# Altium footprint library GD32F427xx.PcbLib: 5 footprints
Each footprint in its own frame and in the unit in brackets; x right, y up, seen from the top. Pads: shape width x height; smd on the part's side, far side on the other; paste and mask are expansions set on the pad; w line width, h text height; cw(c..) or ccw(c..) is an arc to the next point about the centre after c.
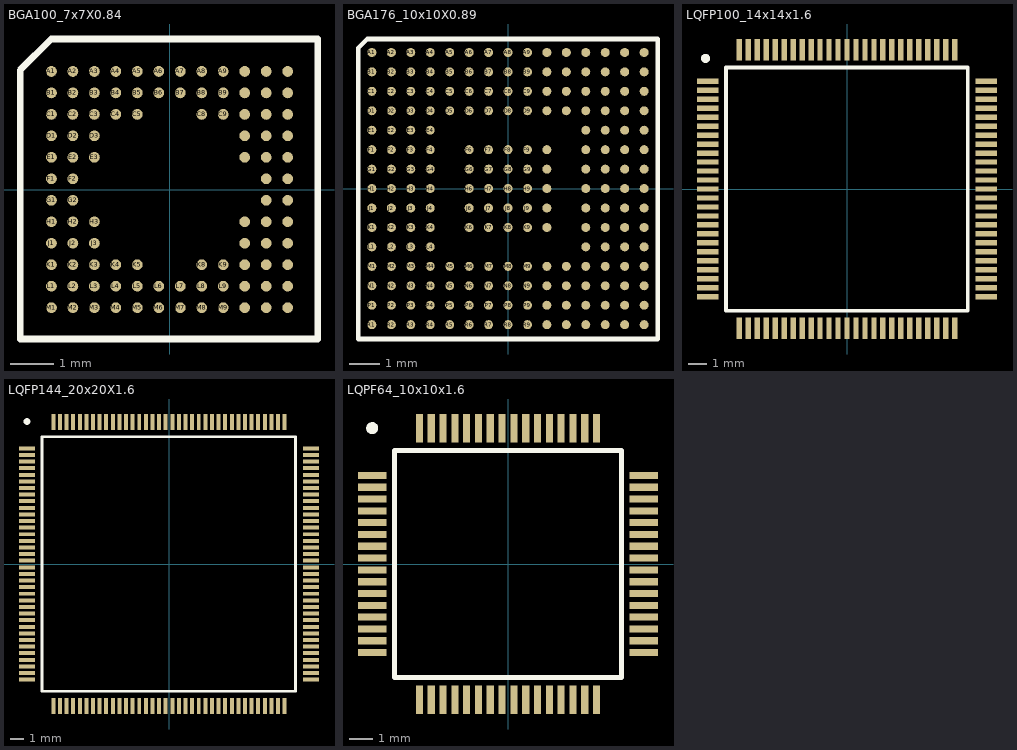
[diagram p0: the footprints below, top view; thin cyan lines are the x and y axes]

## BGA100_7x7X0.84 [mm]
pads (100):
  round 0.25 smd mask+0.05: A1(-2.75,2.75) A2(-2.25,2.75) A3(-1.75,2.75) A4(-1.25,2.75) A5(-0.75,2.75) A6(-0.25,2.75) A7(0.25,2.75) A8(0.75,2.75) A9(1.25,2.75) A10(1.75,2.75) A11(2.25,2.75) A12(2.75,2.75) B1(-2.75,2.25) B2(-2.25,2.25) B3(-1.75,2.25) B4(-1.25,2.25) B5(-0.75,2.25) B6(-0.25,2.25) B7(0.25,2.25) B8(0.75,2.25) B9(1.25,2.25) B10(1.75,2.25) B11(2.25,2.25) B12(2.75,2.25) C1(-2.75,1.75) C2(-2.25,1.75) C3(-1.75,1.75) C4(-1.25,1.75) C5(-0.75,1.75) C8(0.75,1.75) C9(1.25,1.75) C10(1.75,1.75) C11(2.25,1.75) C12(2.75,1.75) D1(-2.75,1.25) D2(-2.25,1.25) D3(-1.75,1.25) D10(1.75,1.25) D11(2.25,1.25) D12(2.75,1.25) E1(-2.75,0.75) E2(-2.25,0.75) E3(-1.75,0.75) E10(1.75,0.75) E11(2.25,0.75) E12(2.75,0.75) F1(-2.75,0.25) F2(-2.25,0.25) F11(2.25,0.25) F12(2.75,0.25) G1(-2.75,-0.25) G2(-2.25,-0.25) G11(2.25,-0.25) G12(2.75,-0.25) H1(-2.75,-0.75) H2(-2.25,-0.75) H3(-1.75,-0.75) H10(1.75,-0.75) H11(2.25,-0.75) H12(2.75,-0.75) J1(-2.75,-1.25) J2(-2.25,-1.25) J3(-1.75,-1.25) J10(1.75,-1.25) J11(2.25,-1.25) J12(2.75,-1.25) K1(-2.75,-1.75) K2(-2.25,-1.75) K3(-1.75,-1.75) K4(-1.25,-1.75) K5(-0.75,-1.75) K8(0.75,-1.75) K9(1.25,-1.75) K10(1.75,-1.75) K11(2.25,-1.75) K12(2.75,-1.75) L1(-2.75,-2.25) L2(-2.25,-2.25) L3(-1.75,-2.25) L4(-1.25,-2.25) L5(-0.75,-2.25) L6(-0.25,-2.25) L7(0.25,-2.25) L8(0.75,-2.25) L9(1.25,-2.25) L10(1.75,-2.25) L11(2.25,-2.25) L12(2.75,-2.25) M1(-2.75,-2.75) M2(-2.25,-2.75) M3(-1.75,-2.75) M4(-1.25,-2.75) M5(-0.75,-2.75) M6(-0.25,-2.75) M7(0.25,-2.75) M8(0.75,-2.75) M9(1.25,-2.75) M10(1.75,-2.75) M11(2.25,-2.75) M12(2.75,-2.75)
Top Overlay:
  lines w0.152: -3.48,-3.48 3.454,-3.48 3.454,3.505 -2.757,3.505 -3.48,2.782 -3.48,-3.48
3D body "BGA100C50P12X12_700X700X84.step": height 0.84, standoff 0, extent -3.5,-3.5 3.5,3.5

## BGA176_10x10X0.89 [mm]
pads (201):
  round 0.3 smd mask+0.05: A1(-4.55,4.55) A2(-3.9,4.55) A3(-3.25,4.55) A4(-2.6,4.55) A5(-1.95,4.55) A6(-1.3,4.55) A7(-0.65,4.55) A8(0,4.55) A9(0.65,4.55) A10(1.3,4.55) A11(1.95,4.55) A12(2.6,4.55) A13(3.25,4.55) A14(3.9,4.55) A15(4.55,4.55) B1(-4.55,3.9) B2(-3.9,3.9) B3(-3.25,3.9) B4(-2.6,3.9) B5(-1.95,3.9) B6(-1.3,3.9) B7(-0.65,3.9) B8(0,3.9) B9(0.65,3.9) B10(1.3,3.9) B11(1.95,3.9) B12(2.6,3.9) B13(3.25,3.9) B14(3.9,3.9) B15(4.55,3.9) C1(-4.55,3.25) C2(-3.9,3.25) C3(-3.25,3.25) C4(-2.6,3.25) C5(-1.95,3.25) C6(-1.3,3.25) C7(-0.65,3.25) C8(0,3.25) C9(0.65,3.25) C10(1.3,3.25) C11(1.95,3.25) C12(2.6,3.25) C13(3.25,3.25) C14(3.9,3.25) C15(4.55,3.25) D1(-4.55,2.6) D2(-3.9,2.6) D3(-3.25,2.6) D4(-2.6,2.6) D5(-1.95,2.6) D6(-1.3,2.6) D7(-0.65,2.6) D8(0,2.6) D9(0.65,2.6) D10(1.3,2.6) D11(1.95,2.6) D12(2.6,2.6) D13(3.25,2.6) D14(3.9,2.6) D15(4.55,2.6) E1(-4.55,1.95) E2(-3.9,1.95) E3(-3.25,1.95) E4(-2.6,1.95) E12(2.6,1.95) E13(3.25,1.95) E14(3.9,1.95) E15(4.55,1.95) F1(-4.55,1.3) F2(-3.9,1.3) F3(-3.25,1.3) F4(-2.6,1.3) F6(-1.3,1.3) F7(-0.65,1.3) F8(0,1.3) F9(0.65,1.3) F10(1.3,1.3) F12(2.6,1.3) F13(3.25,1.3) F14(3.9,1.3) F15(4.55,1.3) G1(-4.55,0.65) G2(-3.9,0.65) G3(-3.25,0.65) G4(-2.6,0.65) G6(-1.3,0.65) G7(-0.65,0.65) G8(0,0.65) G9(0.65,0.65) G10(1.3,0.65) G12(2.6,0.65) G13(3.25,0.65) G14(3.9,0.65) G15(4.55,0.65) H1(-4.55,0) H2(-3.9,0) H3(-3.25,0) H4(-2.6,0) H6(-1.3,0) H7(-0.65,0) H8(0,0) H9(0.65,0) H10(1.3,0) H12(2.6,0) H13(3.25,0) H14(3.9,0) H15(4.55,0) J1(-4.55,-0.65) J2(-3.9,-0.65) J3(-3.25,-0.65) J4(-2.6,-0.65) J6(-1.3,-0.65) J7(-0.65,-0.65) J8(0,-0.65) J9(0.65,-0.65) J10(1.3,-0.65) J12(2.6,-0.65) J13(3.25,-0.65) J14(3.9,-0.65) J15(4.55,-0.65) K1(-4.55,-1.3) K2(-3.9,-1.3) K3(-3.25,-1.3) K4(-2.6,-1.3) K6(-1.3,-1.3) K7(-0.65,-1.3) K8(0,-1.3) K9(0.65,-1.3) K10(1.3,-1.3) K12(2.6,-1.3) K13(3.25,-1.3) K14(3.9,-1.3) K15(4.55,-1.3) L1(-4.55,-1.95) L2(-3.9,-1.95) L3(-3.25,-1.95) L4(-2.6,-1.95) L12(2.6,-1.95) L13(3.25,-1.95) L14(3.9,-1.95) L15(4.55,-1.95) M1(-4.55,-2.6) M2(-3.9,-2.6) M3(-3.25,-2.6) M4(-2.6,-2.6) M5(-1.95,-2.6) M6(-1.3,-2.6) M7(-0.65,-2.6) M8(0,-2.6) M9(0.65,-2.6) M10(1.3,-2.6) M11(1.95,-2.6) M12(2.6,-2.6) M13(3.25,-2.6) M14(3.9,-2.6) M15(4.55,-2.6) N1(-4.55,-3.25) N2(-3.9,-3.25) N3(-3.25,-3.25) N4(-2.6,-3.25) N5(-1.95,-3.25) N6(-1.3,-3.25) N7(-0.65,-3.25) N8(0,-3.25) N9(0.65,-3.25) N10(1.3,-3.25) N11(1.95,-3.25) N12(2.6,-3.25) N13(3.25,-3.25) N14(3.9,-3.25) N15(4.55,-3.25) P1(-4.55,-3.9) P2(-3.9,-3.9) P3(-3.25,-3.9) P4(-2.6,-3.9) P5(-1.95,-3.9) P6(-1.3,-3.9) P7(-0.65,-3.9) P8(0,-3.9) P9(0.65,-3.9) P10(1.3,-3.9) P11(1.95,-3.9) P12(2.6,-3.9) P13(3.25,-3.9) P14(3.9,-3.9) P15(4.55,-3.9) R1(-4.55,-4.55) R2(-3.9,-4.55) R3(-3.25,-4.55) R4(-2.6,-4.55) R5(-1.95,-4.55) R6(-1.3,-4.55) R7(-0.65,-4.55) R8(0,-4.55) R9(0.65,-4.55) R10(1.3,-4.55) R11(1.95,-4.55) R12(2.6,-4.55) R13(3.25,-4.55) R14(3.9,-4.55) R15(4.55,-4.55)
Top Overlay:
  lines w0.152: -5.004,-5.029 -5.004,4.699 -4.703,5 5.004,5 5.004,-5.029 -5.004,-5.029
3D body "BGA176C65P15X15_1000X1000X89.step": height 0.89, standoff 0, extent -5,-5 5,5

## LQFP100_14x14x1.6 [mm]
pads (100):
  rect 1.2x0.3 smd: 1(-7.75,6) 2(-7.75,5.5) 3(-7.75,5) 4(-7.75,4.5) 5(-7.75,4) 6(-7.75,3.5) 7(-7.75,3) 8(-7.75,2.5) 9(-7.75,2) 10(-7.75,1.5) 11(-7.75,1) 12(-7.75,0.5) 13(-7.75,0) 14(-7.75,-0.5) 15(-7.75,-1) 16(-7.75,-1.5) 17(-7.75,-2) 18(-7.75,-2.5) 19(-7.75,-3) 20(-7.75,-3.5) 21(-7.75,-4) 22(-7.75,-4.5) 23(-7.75,-5) 24(-7.75,-5.5) 25(-7.75,-6) 51(7.75,-6) 52(7.75,-5.5) 53(7.75,-5) 54(7.75,-4.5) 55(7.75,-4) 56(7.75,-3.5) 57(7.75,-3) 58(7.75,-2.5) 59(7.75,-2) 60(7.75,-1.5) 61(7.75,-1) 62(7.75,-0.5) 63(7.75,0) 64(7.75,0.5) 65(7.75,1) 66(7.75,1.5) 67(7.75,2) 68(7.75,2.5) 69(7.75,3) 70(7.75,3.5) 71(7.75,4) 72(7.75,4.5) 73(7.75,5) 74(7.75,5.5) 75(7.75,6)
  rect 0.3x1.2 smd: 26(-6,-7.75) 27(-5.5,-7.75) 28(-5,-7.75) 29(-4.5,-7.75) 30(-4,-7.75) 31(-3.5,-7.75) 32(-3,-7.75) 33(-2.5,-7.75) 34(-2,-7.75) 35(-1.5,-7.75) 36(-1,-7.75) 37(-0.5,-7.75) 38(0,-7.75) 39(0.5,-7.75) 40(1,-7.75) 41(1.5,-7.75) 42(2,-7.75) 43(2.5,-7.75) 44(3,-7.75) 45(3.5,-7.75) 46(4,-7.75) 47(4.5,-7.75) 48(5,-7.75) 49(5.5,-7.75) 50(6,-7.75) 76(6,7.75) 77(5.5,7.75) 78(5,7.75) 79(4.5,7.75) 80(4,7.75) 81(3.5,7.75) 82(3,7.75) 83(2.5,7.75) 84(2,7.75) 85(1.5,7.75) 86(1,7.75) 87(0.5,7.75) 88(0,7.75) 89(-0.5,7.75) 90(-1,7.75) 91(-1.5,7.75) 92(-2,7.75) 93(-2.5,7.75) 94(-3,7.75) 95(-3.5,7.75) 96(-4,7.75) 97(-4.5,7.75) 98(-5,7.75) 99(-5.5,7.75) 100(-6,7.75)
Top Overlay:
  circle w0.254: c-7.877,7.27 r0.127
  lines w0.203: -6.734,-6.782 6.728,-6.782 6.728,6.762 -6.734,6.762 -6.734,-6.782
3D body "TSQFP50P1600X1600X160-100N.step": height 1.6, standoff 0, extent -8,-8 8,8

## LQFP144_20x20X1.6 [mm]
pads (144):
  rect 1.2x0.3 smd: 1(-10.75,8.75) 2(-10.75,8.25) 3(-10.75,7.75) 4(-10.75,7.25) 5(-10.75,6.75) 6(-10.75,6.25) 7(-10.75,5.75) 8(-10.75,5.25) 9(-10.75,4.75) 10(-10.75,4.25) 11(-10.75,3.75) 12(-10.75,3.25) 13(-10.75,2.75) 14(-10.75,2.25) 15(-10.75,1.75) 16(-10.75,1.25) 17(-10.75,0.75) 18(-10.75,0.25) 19(-10.75,-0.25) 20(-10.75,-0.75) 21(-10.75,-1.25) 22(-10.75,-1.75) 23(-10.75,-2.25) 24(-10.75,-2.75) 25(-10.75,-3.25) 26(-10.75,-3.75) 27(-10.75,-4.25) 28(-10.75,-4.75) 29(-10.75,-5.25) 30(-10.75,-5.75) 31(-10.75,-6.25) 32(-10.75,-6.75) 33(-10.75,-7.25) 34(-10.75,-7.75) 35(-10.75,-8.25) 36(-10.75,-8.75) 73(10.75,-8.75) 74(10.75,-8.25) 75(10.75,-7.75) 76(10.75,-7.25) 77(10.75,-6.75) 78(10.75,-6.25) 79(10.75,-5.75) 80(10.75,-5.25) 81(10.75,-4.75) 82(10.75,-4.25) 83(10.75,-3.75) 84(10.75,-3.25) 85(10.75,-2.75) 86(10.75,-2.25) 87(10.75,-1.75) 88(10.75,-1.25) 89(10.75,-0.75) 90(10.75,-0.25) 91(10.75,0.25) 92(10.75,0.75) 93(10.75,1.25) 94(10.75,1.75) 95(10.75,2.25) 96(10.75,2.75) 97(10.75,3.25) 98(10.75,3.75) 99(10.75,4.25) 100(10.75,4.75) 101(10.75,5.25) 102(10.75,5.75) 103(10.75,6.25) 104(10.75,6.75) 105(10.75,7.25) 106(10.75,7.75) 107(10.75,8.25) 108(10.75,8.75)
  rect 0.3x1.2 smd: 37(-8.75,-10.75) 38(-8.25,-10.75) 39(-7.75,-10.75) 40(-7.25,-10.75) 41(-6.75,-10.75) 42(-6.25,-10.75) 43(-5.75,-10.75) 44(-5.25,-10.75) 45(-4.75,-10.75) 46(-4.25,-10.75) 47(-3.75,-10.75) 48(-3.25,-10.75) 49(-2.75,-10.75) 50(-2.25,-10.75) 51(-1.75,-10.75) 52(-1.25,-10.75) 53(-0.75,-10.75) 54(-0.25,-10.75) 55(0.25,-10.75) 56(0.75,-10.75) 57(1.25,-10.75) 58(1.75,-10.75) 59(2.25,-10.75) 60(2.75,-10.75) 61(3.25,-10.75) 62(3.75,-10.75) 63(4.25,-10.75) 64(4.75,-10.75) 65(5.25,-10.75) 66(5.75,-10.75) 67(6.25,-10.75) 68(6.75,-10.75) 69(7.25,-10.75) 70(7.75,-10.75) 71(8.25,-10.75) 72(8.75,-10.75) 109(8.75,10.75) 110(8.25,10.75) 111(7.75,10.75) 112(7.25,10.75) 113(6.75,10.75) 114(6.25,10.75) 115(5.75,10.75) 116(5.25,10.75) 117(4.75,10.75) 118(4.25,10.75) 119(3.75,10.75) 120(3.25,10.75) 121(2.75,10.75) 122(2.25,10.75) 123(1.75,10.75) 124(1.25,10.75) 125(0.75,10.75) 126(0.25,10.75) 127(-0.25,10.75) 128(-0.75,10.75) 129(-1.25,10.75) 130(-1.75,10.75) 131(-2.25,10.75) 132(-2.75,10.75) 133(-3.25,10.75) 134(-3.75,10.75) 135(-4.25,10.75) 136(-4.75,10.75) 137(-5.25,10.75) 138(-5.75,10.75) 139(-6.25,10.75) 140(-6.75,10.75) 141(-7.25,10.75) 142(-7.75,10.75) 143(-8.25,10.75) 144(-8.75,10.75)
Top Overlay:
  circle w0.254: c-10.75,10.782 r0.127
  lines w0.203: -9.607,-9.627 -9.607,9.639 9.57,9.639 9.57,-9.627 -9.607,-9.627
3D body "TSQFP50P2200X2200X160-144N.step": height 1.6, standoff 0, extent -11,-11 11,11

## LQPF64_10x10x1.6 [mm]
pads (64):
  rect 1.2x0.3 smd: 1(-5.75,3.75) 2(-5.75,3.25) 3(-5.75,2.75) 4(-5.75,2.25) 5(-5.75,1.75) 6(-5.75,1.25) 7(-5.75,0.75) 8(-5.75,0.25) 9(-5.75,-0.25) 10(-5.75,-0.75) 11(-5.75,-1.25) 12(-5.75,-1.75) 13(-5.75,-2.25) 14(-5.75,-2.75) 15(-5.75,-3.25) 16(-5.75,-3.75) 33(5.75,-3.75) 34(5.75,-3.25) 35(5.75,-2.75) 36(5.75,-2.25) 37(5.75,-1.75) 38(5.75,-1.25) 39(5.75,-0.75) 40(5.75,-0.25) 41(5.75,0.25) 42(5.75,0.75) 43(5.75,1.25) 44(5.75,1.75) 45(5.75,2.25) 46(5.75,2.75) 47(5.75,3.25) 48(5.75,3.75)
  rect 0.3x1.2 smd: 17(-3.75,-5.75) 18(-3.25,-5.75) 19(-2.75,-5.75) 20(-2.25,-5.75) 21(-1.75,-5.75) 22(-1.25,-5.75) 23(-0.75,-5.75) 24(-0.25,-5.75) 25(0.25,-5.75) 26(0.75,-5.75) 27(1.25,-5.75) 28(1.75,-5.75) 29(2.25,-5.75) 30(2.75,-5.75) 31(3.25,-5.75) 32(3.75,-5.75) 49(3.75,5.75) 50(3.25,5.75) 51(2.75,5.75) 52(2.25,5.75) 53(1.75,5.75) 54(1.25,5.75) 55(0.75,5.75) 56(0.25,5.75) 57(-0.25,5.75) 58(-0.75,5.75) 59(-1.25,5.75) 60(-1.75,5.75) 61(-2.25,5.75) 62(-2.75,5.75) 63(-3.25,5.75) 64(-3.75,5.75)
Top Overlay:
  circle w0.254: c-5.75,5.75 r0.127
  lines w0.203: -4.801,-4.801 -4.801,4.801 4.801,4.801 4.801,-4.801 -4.801,-4.801
3D body "TSQFP50P1200X1200X160-64N.step": height 1.6, standoff 0, extent -6,-6 6,6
